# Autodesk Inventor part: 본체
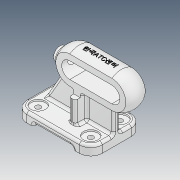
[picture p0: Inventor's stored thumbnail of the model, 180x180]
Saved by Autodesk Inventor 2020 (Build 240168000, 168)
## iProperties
Created: 2025-01
Part Number: 본체
Material: 알루미늄 6061
Document SubType Name: Modeling
Designer: 1강의실14
Density: 2.7 g/cm^3
Appearance: 알루미늄 - 평지
Mass: 346.087 g
Surface Area: 333.559 cm^2
Volume: 128.18 cm^3
Author: 1강의실14
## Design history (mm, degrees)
sketch "스케치1"
  geometry: L1 (-26, 42)-(26, 42); L2 (26, 42)-(26, 0); L3 (26, 0)-(-26, 0); L4 (-26, 0)-(-26, 42); L5 (-47, 21)-(47, 21); A1 r 21 centre (-26, 21) between (-26, 42) and (-47, 21); A2 r 21 centre (26, 21) between (26, 0) and (47, 21); A3 r 21 centre (26, 21) between (47, 21) and (26, 42); A4 r 21 centre (-26, 21) between (-47, 21) and (-26, 0); 1 further point
  constraints: 10 end point, 8 point on circle, 4 centre point, 4 tangent, 3 parallel, 1 horizontal, 1 midpoint, 1 perpendicular
  dimensions: "d31" = 52 distance of L1.start L1.end; "d32" = 42 distance of L1.end L2.end; "d33" = 26 distance from line of point (0, 0) L4; "d34" = 21 radius of A2 (derived); "d35" = 42 diameter of L1 L5
revolve "회전1" sketch "스케치1" stored, may be unused: angle "d36" = 90 deg
sketch "스케치3"
  geometry: L1 (-73, -30)-(20, -30); L2 (20, -30)-(20, -42); L3 (20, -42)-(-73, -42); L4 (-73, -42)-(-73, -30); A1 r 21 centre (26, 21) between (26, 0) and (26, 42) reference; A2 r 21 centre (-26, 21) between (-26, 42) and (-26, 0) reference; 1 further point
  constraints: 8 end point, 2 parallel, 1 horizontal, 1 perpendicular
  dimensions: "d37" = 12 distance of L1.end L2.end; "d38" = 93 distance of L2.end L3.end; "d39" = 6 distance from line of A1.centre L2; "d40" = 63 distance from line of A1.centre L3
extrude "돌출3" join sketch "스케치3" stored distance "d41" = 64; taper "d42" = 0 deg
node "작업 평면1"
sketch "스케치5"
  geometry: L1 (14, 52.183)-(14, 12); L2 (50, 52.183)-(50, 12); L3 (64, 12)-(0, 12) reference; A1 r 21 centre (32, 63) between (32, 42) and (14, 52.183) reference
  constraints: 4 end point, 2 point on circle, 2 point on line, 2 vertical
  dimensions: "d46" = 18 distance from line of A1.centre L1; "d47" = 36 distance between parallel lines of L2 L1
extrude "돌출5" join sketch "스케치5" distance "d48" = 8; taper "d49" = 0 deg
sketch "스케치6"
  geometry: L1 (-26, 0)-(26, 0) reference; L2 (-73, -30)-(20, -30) reference; L3 (-42.241, 7.687)-(-64, -30); L4 (20, 0)-(20, -30); L5 (-73, -42)-(-73, -30) reference; A1 r 21 centre (-26, 21) between (-26, 42) and (-26, 0) reference; 1 further point
  constraints: 4 end point, 2 point on line, 1 point on circle, 1 vertical
  dimensions: "d50" = 60 deg angle of L2 L3; "d51" = 9 distance from line of L3.end L5
feature "리브1" dims "d52" = 1, "d53" = 8, "d54" = 0, "d55" = 0, "d56" = 1, "d57" = 1
feature "리브2" dims "d58" = 1, "d59" = 8, "d60" = 0, "d61" = 0, "d62" = 1, "d63" = 1
node "작업 평면2"
sketch "스케치8"
  geometry: L1 (-52.358, 42)-(60.236, 42); L2 (60.236, 42)-(60.236, -2); L3 (60.236, -2)-(-52.358, -2); L4 (-52.358, -2)-(-52.358, 42); L5 (20, -42)-(-73, -42) reference; 1 further point
  constraints: 8 end point, 2 parallel, 1 horizontal, 1 perpendicular
  dimensions: "d65" = 44 distance of L1.end L2.end; "d66" = 84 distance between parallel lines of L5 L1; "d67" = 112.5939 distance of L1.start L1.end; "d68" = 52.35808 distance from line of point (0, 0) L4
extrude "돌출6" cut sketch "스케치8" distance "d69" = 24.5; taper "d70" = 0 deg
sketch "스케치9"
  geometry: L1 (-26, 21)-(26, 21); L2 (-26, 11)-(26, 11); L3 (26, 31)-(-26, 31); A1 r 21 centre (-26, 21) between (-26, 42) and (-42.241, 7.687) reference; A2 r 21 centre (26, 21) between (26, 0) and (26, 42) reference; A3 r 10 centre (-26, 21) between (-26, 31) and (-26, 11); A4 r 10 centre (26, 21) between (26, 11) and (26, 31); 2 further points
  constraints: 8 end point, 4 point on circle, 4 tangent, 2 centre point, 1 horizontal, 1 midpoint, 1 parallel
  dimensions: "d72" = 20 diameter of A4
extrude "돌출7" cut sketch "스케치9" stored distance "d73" = 24; taper "d74" = 0 deg
sketch "스케치10"
  geometry: L1 (0, 64)-(0, 0) reference; L2 (93, 64)-(0, 64) reference; L3 (93, 64)-(93, 0) reference; L4 (0, 0)-(93, 0) reference; L5 (0, 64)-(0, 0) reference; L6 (93, 64)-(0, 64) reference; 2 further points
  dimensions: "d75" = 14 distance from line of point (14, 50) L1; "d76" = 18 vertical distance of point (73, 32) point (14, 50)
hole "구멍1" sketch "스케치10" at (14, 50) diameter "d77" = 6.6; stored, may be unused: countersink angle "d81" = 90 deg, drill point angle "d83" = 0 deg; dims "d78" = 12, "d79" = 4, "d80" = 2, "d82" = 15
sketch "스케치11"
  geometry: C1 r 3.3 at (14, 50) reference; C2 r 9 at (14, 50); 1 further point
  constraints: 1 centre point, 1 coincident
  dimensions: "d85" = 18 diameter of C2
extrude "돌출8" cut sketch "스케치11" distance "d86" = 2; taper "d87" = 0 deg
sketch "스케치12"
  geometry: L1 (0, -64)-(0, 0) reference; L2 (93, -64)-(93, 0) reference; L3 (22, 0)-(71, 0); L4 (71, 0)-(71, -64); L5 (71, -64)-(22, -64); L6 (22, -64)-(22, 0); 1 further point
  constraints: 8 end point, 2 parallel, 1 horizontal, 1 perpendicular
  dimensions: "d94" = 22 distance between parallel lines of L2 L4; "d95" = 22 distance between parallel lines of L6 L1; "d96" = 64 distance between parallel lines of L5 L3; "d97" = 32 distance from line of point (73, -32) L3
extrude "돌출9" cut sketch "스케치12" distance "d98" = 3; taper "d99" = 0 deg
fillet "모깎기1" dims "d100" = 14
fillet "모깎기2" dims "d101" = 3
node "작업 평면3"
sketch "스케치13"
  geometry: C1 r 8 at (-21, 0); A1 r 21 centre (-21, 0) between (-38.234, 12) and (-38.234, -12) reference; 1 further point
  constraints: 1 centre point, 1 coincident
  dimensions: "d103" = 16 diameter of C1
extrude "돌출10" join sketch "스케치13" stored distance "d104" = 3; taper "d105" = 0 deg
sketch "스케치14"
  geometry: C1 r 8 at (0, 0) reference; C2 r 4.5 at (0, 0); 1 further point
  constraints: 1 centre point, 1 coincident
  dimensions: "d106" = 9 diameter of C2
extrude "돌출11" cut sketch "스케치14" distance "d107" = 22.25; taper "d108" = 0 deg
fillet "모깎기3" dims "d109" = 3
fillet "모깎기4" dims "d110" = 3
fillet "모깎기5" dims "d111" = 3
fillet "모깎기6" dims "d112" = 3
fillet "모깎기7" dims "d113" = 3
fillet "모깎기8" dims "d114" = 3
node "작업 평면4"
sketch "스케치15"
  geometry: L1 (-26, 12)-(-26, -12) reference; 2 further points
  constraints: 1 coincident, 1 other
  dimensions: "d115" = 26 distance from line of L1 point (0, 0)
feature "엠보싱1" sketch "스케치15" dims "d31" = 52, "d32" = 42, "d33" = 26, "d34" = 21 (derived), "d35" = 42, "d37" = 12, "d38" = 93, "d39" = 6, "d40" = 63, "d116" = 0.5, "d117" = 0
fillet "모깎기9" dims "d118" = 3
node "솔리드1"
mirror "미러1"
pattern_linear "직사각형 패턴1" dims "d90" = 65, "d93" = 36
node "솔리드2"
node "투영된 루프1"
feature "A9D066F2-1C7D-4E18-AEED-F7BC21143FA4" dims "d77" = 6.6, "d78" = 12, "d79" = 4, "d80" = 2, "d81" = 90 deg, "d82" = 15, "d83" = 0
other parameters: "d43" = -33, "d64" = 12
